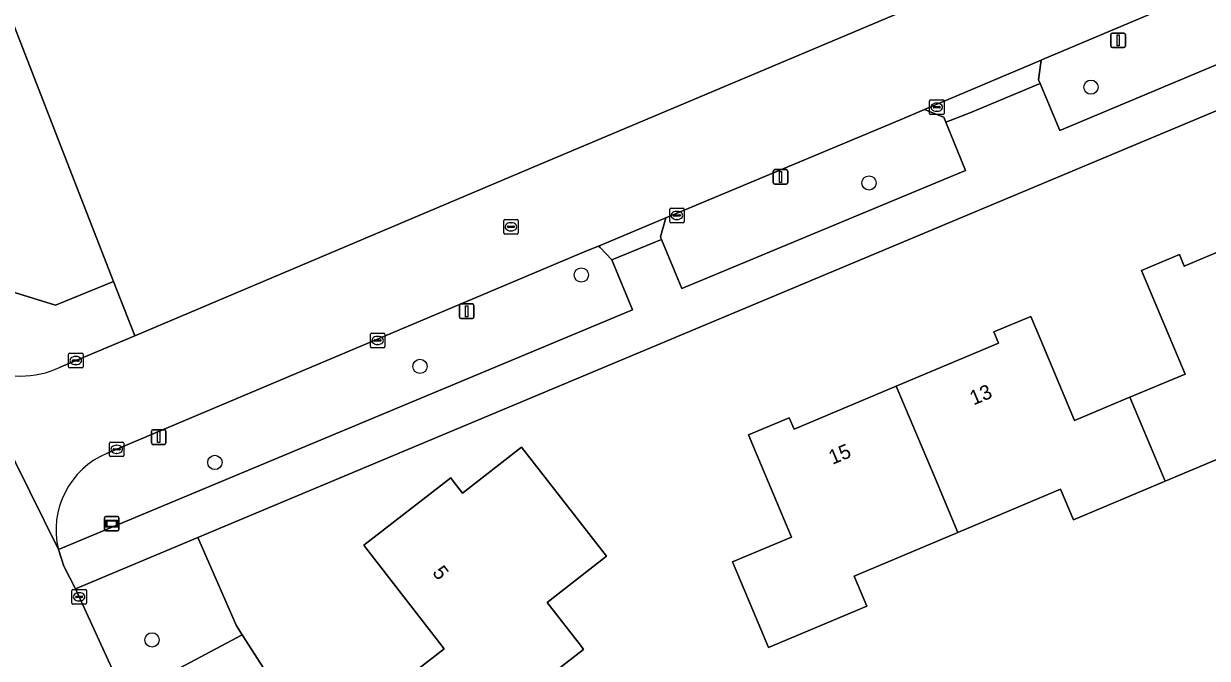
# Model space of a CAD drawing. Extents: x 162417 to 163722, y 384268 to 385417.
# Drawn here: x 163351.6 to 163432.7, y 384965.6 to 385009.1 of the extents above; entities that cross this region are included whole.
import ezdxf

# ---------------------------------------------------------------- set-up
doc = ezdxf.new("R2010")
doc.units = 0
for name, color, linetype in [('IMGEO_Berm_groen', 7, 'Continuous'), ('IMGEO_Boom', 7, 'Continuous'), ('IMGEO_Erf', 7, 'Continuous'), ('IMGEO_Groenvoorziening', 7, 'Continuous'), ('IMGEO_Kolk', 7, 'Continuous'), ('IMGEO_Lichtmast', 7, 'Continuous'), ('IMGEO_Loofbos', 7, 'Continuous'), ('IMGEO_Pand', 7, 'Continuous'), ('IMGEO_Pand_nummerreeks', 7, 'Continuous'), ('IMGEO_Rijbaan_lokaal_gesloten', 7, 'Continuous'), ('IMGEO_Rioolput', 7, 'Continuous'), ('IMGEO_Verklikker', 7, 'Continuous'), ('IMGEO_Voetpad_open', 7, 'Continuous')]:
    doc.layers.add(name, color=color, linetype=linetype)

msp = doc.modelspace()

# ---------------------------------------------------------------- linework, layer by layer
at = {"layer": 'IMGEO_Berm_groen'}
for points in [[(163354.083, 384985.536), (163359.186, 384987.697), (163357.745, 384991.405), (163353.753, 384989.786), (163350.645, 384990.763), (163348.459, 384993.49), (163345.34, 385000), (163325.132, 385042.177)], [(163393.318, 384989.467), (163391.91, 384992.911), (163391.091, 384993.737), (163390.981, 384993.848), (163390.13, 384993.491), (163357.952, 384979.9), (163357.313, 384979.632)], [(163353.956, 384973.02), (163393.318, 384989.467)]]:
    msp.add_lwpolyline(points, dxfattribs=at)
msp.add_lwpolyline([(163442.302, 385013.957), (163442.198, 385014.207), (163441.445, 385014.752), (163441.213, 385014.921), (163429.137, 385009.898), (163421.429, 385006.64), (163421.331, 385006.599), (163421.165, 385005.249), (163421.266, 385005.008), (163422.621, 385001.771), (163443.689, 385010.64)], close=True, dxfattribs=at)
for centre, radius, start, end in [((163351.397, 384991.135), 6.21, 243.35069, 295.62302), ((163359.493, 384974.367), 5.698, 112.49155, 193.67343)]:
    msp.add_arc(centre, radius, start, end, dxfattribs=at)
at = {"layer": 'IMGEO_Boom'}
for centre in [(163424.753, 385004.752), (163409.535, 384998.178), (163389.81, 384991.862), (163378.747, 384985.59), (163364.685, 384978.999), (163360.375, 384966.821)]:
    msp.add_circle(centre, 0.489, dxfattribs=at)
at = {"layer": 'IMGEO_Erf'}
for points in [[(163526.981, 385058.237), (163524.402, 385063.53), (163507.868, 385095.856), (163500, 385092.556), (163419.878, 385059.084), (163371.144, 385038.583), (163343.981, 385026.826), (163354.406, 385000), (163357.745, 384991.405), (163359.186, 384987.697), (163387.545, 384999.704), (163388.243, 385000), (163425.932, 385015.904), (163500, 385046.827), (163524.917, 385057.312)], [(163383.993, 384961.544), (163380.314, 384958.697), (163380.225, 384958.812), (163376.874, 384963.141), (163376.718, 384963.343), (163380.414, 384966.203), (163375.046, 384973.139), (163374.9, 384973.327), (163380.856, 384977.937), (163381.023, 384977.723), (163381.669, 384976.895), (163385.708, 384980.043), (163391.542, 384972.558), (163387.465, 384969.38), (163389.817, 384966.363), (163389.969, 384966.169)]]:
    msp.add_lwpolyline(points, close=True, dxfattribs=at)
for points in [[(163571.782, 384971.962), (163557.559, 385000), (163534.443, 385045.503), (163500, 385031.078), (163425.859, 385000), (163365.371, 384974.629), (163363.507, 384973.847), (163366.161, 384967.778), (163366.55, 384967.171), (163368.242, 384964.531)], [(163436.151, 384980.365), (163429.839, 384977.706), (163423.549, 384975.056), (163422.664, 384977.156), (163415.628, 384974.192), (163408.509, 384971.193), (163409.376, 384969.136), (163402.648, 384966.302), (163402.116, 384967.566), (163400.175, 384972.173), (163404.216, 384973.876), (163401.795, 384979.625), (163401.263, 384980.887), (163404.062, 384982.066), (163404.393, 384981.278), (163411.402, 384984.231), (163418.408, 384987.182), (163418.084, 384987.951), (163420.62, 384989.019), (163421.195, 384987.655), (163423.631, 384981.873), (163427.308, 384983.422), (163427.415, 384983.467), (163431.202, 384985.062), (163428.209, 384992.166), (163430.816, 384993.264), (163431.151, 384992.468), (163438.083, 384995.389)]]:
    msp.add_lwpolyline(points, dxfattribs=at)
at = {"layer": 'IMGEO_Groenvoorziening'}
for points in [[(163416.143, 384999.038), (163414.794, 385002.353), (163414.657, 385002.69), (163414.525, 385002.749), (163413.564, 385003.127), (163413.331, 385003.218), (163411.617, 385002.494), (163395.6, 384995.783), (163395.23, 384994.489), (163395.315, 384994.288), (163396.712, 384990.944)], [(163363.507, 384973.847), (163355.13, 384970.334), (163358.119, 384963.778), (163359.376, 384963.356), (163366.55, 384967.171), (163366.161, 384967.778)]]:
    msp.add_lwpolyline(points, close=True, dxfattribs=at)
at = {"layer": 'IMGEO_Kolk'}
for p, q in [((163413.678, 385002.947), (163413.678, 385003.799)), ((163413.753, 385003.873), (163414.605, 385003.873)), ((163413.937, 385003.367), (163413.937, 385003.379)), ((163414.375, 385003.33), (163413.977, 385003.33)), ((163413.98, 385003.416), (163414.378, 385003.416)), ((163414.166, 385003.653), (163414.191, 385003.653)), ((163414.421, 385003.379), (163414.421, 385003.367)), ((163414.679, 385003.799), (163414.679, 385002.947)), ((163414.605, 385002.873), (163413.753, 385002.873)), ((163414.189, 385003.093), (163414.164, 385003.093)), ((163395.868, 384995.524), (163395.868, 384996.376)), ((163395.943, 384996.45), (163396.795, 384996.45)), ((163396.356, 384996.23), (163396.381, 384996.23)), ((163396.869, 384996.376), (163396.869, 384995.524)), ((163396.795, 384995.45), (163395.943, 384995.45)), ((163396.127, 384995.944), (163396.127, 384995.956)), ((163396.565, 384995.907), (163396.167, 384995.907)), ((163396.17, 384995.993), (163396.568, 384995.993)), ((163396.379, 384995.67), (163396.354, 384995.67)), ((163396.611, 384995.956), (163396.611, 384995.944)), ((163375.345, 384986.944), (163375.345, 384987.796)), ((163375.42, 384987.87), (163376.272, 384987.87)), ((163375.604, 384987.364), (163375.604, 384987.376)), ((163376.042, 384987.327), (163375.644, 384987.327)), ((163375.647, 384987.413), (163376.045, 384987.413)), ((163375.856, 384987.09), (163375.831, 384987.09)), ((163375.833, 384987.65), (163375.858, 384987.65)), ((163376.088, 384987.376), (163376.088, 384987.364)), ((163376.346, 384987.796), (163376.346, 384986.944)), ((163354.644, 384985.563), (163354.644, 384986.415)), ((163354.719, 384986.489), (163355.571, 384986.489)), ((163355.132, 384986.269), (163355.157, 384986.269)), ((163355.645, 384986.415), (163355.645, 384985.563)), ((163376.272, 384986.87), (163375.42, 384986.87)), ((163355.571, 384985.489), (163354.719, 384985.489)), ((163354.903, 384985.983), (163354.903, 384985.995)), ((163355.341, 384985.946), (163354.943, 384985.946)), ((163354.946, 384986.032), (163355.344, 384986.032)), ((163355.155, 384985.709), (163355.13, 384985.709)), ((163355.387, 384985.995), (163355.387, 384985.983)), ((163357.451, 384979.474), (163357.451, 384980.326)), ((163357.526, 384980.4), (163358.378, 384980.4)), ((163357.71, 384979.894), (163357.71, 384979.906)), ((163358.148, 384979.857), (163357.75, 384979.857)), ((163357.753, 384979.943), (163358.151, 384979.943)), ((163357.939, 384980.18), (163357.964, 384980.18)), ((163358.194, 384979.906), (163358.194, 384979.894)), ((163358.452, 384980.326), (163358.452, 384979.474)), ((163358.378, 384979.4), (163357.526, 384979.4)), ((163357.962, 384979.62), (163357.937, 384979.62)), ((163354.878, 384969.351), (163354.878, 384970.203)), ((163354.953, 384970.277), (163355.805, 384970.277)), ((163355.366, 384970.057), (163355.391, 384970.057)), ((163355.879, 384970.203), (163355.879, 384969.351)), ((163355.805, 384969.277), (163354.953, 384969.277)), ((163355.137, 384969.771), (163355.137, 384969.783)), ((163355.575, 384969.734), (163355.177, 384969.734)), ((163355.18, 384969.82), (163355.578, 384969.82)), ((163355.389, 384969.497), (163355.364, 384969.497)), ((163355.621, 384969.783), (163355.621, 384969.771))]:
    msp.add_line(p, q, dxfattribs=at)
for points in [[(163413.678, 385002.947), (163413.678, 385003.799)], [(163413.753, 385003.873), (163414.605, 385003.873)], [(163414.679, 385003.799), (163414.679, 385002.947)], [(163414.605, 385002.873), (163413.753, 385002.873)], [(163395.868, 384995.524), (163395.868, 384996.376)], [(163395.943, 384996.45), (163396.795, 384996.45)], [(163396.869, 384996.376), (163396.869, 384995.524)], [(163396.795, 384995.45), (163395.943, 384995.45)], [(163375.345, 384986.944), (163375.345, 384987.796)], [(163375.42, 384987.87), (163376.272, 384987.87)], [(163376.346, 384987.796), (163376.346, 384986.944)], [(163354.644, 384985.563), (163354.644, 384986.415)], [(163354.719, 384986.489), (163355.571, 384986.489)], [(163355.645, 384986.415), (163355.645, 384985.563)], [(163376.272, 384986.87), (163375.42, 384986.87)], [(163355.571, 384985.489), (163354.719, 384985.489)], [(163357.451, 384979.474), (163357.451, 384980.326)], [(163357.526, 384980.4), (163358.378, 384980.4)], [(163358.452, 384980.326), (163358.452, 384979.474)], [(163358.378, 384979.4), (163357.526, 384979.4)], [(163354.878, 384969.351), (163354.878, 384970.203)], [(163354.953, 384970.277), (163355.805, 384970.277)], [(163355.879, 384970.203), (163355.879, 384969.351)], [(163355.805, 384969.277), (163354.953, 384969.277)]]:
    msp.add_lwpolyline(points, dxfattribs=at)
for centre, radius, start, end in [((163413.755, 385003.797), 0.0765, 91.55205, 178.44795), ((163413.755, 385003.797), 0.0765, 91.55205, 178.44795), ((163413.977, 385003.376), 0.0403, 85.87752, 175.75265), ((163413.974, 385003.366), 0.0366, 178.93798, 274.71019), ((163414.378, 385003.373), 0.043, 264.86636, 352.45326), ((163414.382, 385003.378), 0.0386, 1.73085, 96.63898), ((163414.603, 385003.797), 0.0765, 1.55205, 88.44795), ((163414.603, 385003.797), 0.0765, 1.55205, 88.44795), ((163413.755, 385002.949), 0.0765, 181.55205, 268.44795), ((163413.755, 385002.949), 0.0765, 181.55205, 268.44795), ((163414.603, 385002.949), 0.0765, 271.55205, 358.44795), ((163414.603, 385002.949), 0.0765, 271.55205, 358.44795), ((163395.945, 384996.374), 0.0765, 91.55205, 178.44795), ((163395.945, 384996.374), 0.0765, 91.55205, 178.44795), ((163396.793, 384996.374), 0.0765, 1.55205, 88.44795), ((163396.793, 384996.374), 0.0765, 1.55205, 88.44795), ((163395.945, 384995.526), 0.0765, 181.55205, 268.44795), ((163395.945, 384995.526), 0.0765, 181.55205, 268.44795), ((163396.167, 384995.953), 0.0403, 85.87752, 175.75265), ((163396.164, 384995.943), 0.0366, 178.93798, 274.71019), ((163396.568, 384995.95), 0.043, 264.86636, 352.45326), ((163396.572, 384995.955), 0.0386, 1.73085, 96.63898), ((163396.793, 384995.526), 0.0765, 271.55205, 358.44795), ((163396.793, 384995.526), 0.0765, 271.55205, 358.44795), ((163375.422, 384987.794), 0.0765, 91.55205, 178.44795), ((163375.422, 384987.794), 0.0765, 91.55205, 178.44795), ((163375.644, 384987.373), 0.0403, 85.87752, 175.75265), ((163375.641, 384987.363), 0.0366, 178.93798, 274.71019), ((163376.045, 384987.37), 0.043, 264.86636, 352.45326), ((163376.049, 384987.375), 0.0386, 1.73085, 96.63898), ((163376.27, 384987.794), 0.0765, 1.55205, 88.44795), ((163376.27, 384987.794), 0.0765, 1.55205, 88.44795), ((163354.721, 384986.413), 0.0765, 91.55205, 178.44795), ((163354.721, 384986.413), 0.0765, 91.55205, 178.44795), ((163355.569, 384986.413), 0.0765, 1.55205, 88.44795), ((163355.569, 384986.413), 0.0765, 1.55205, 88.44795), ((163375.422, 384986.946), 0.0765, 181.55205, 268.44795), ((163375.422, 384986.946), 0.0765, 181.55205, 268.44795), ((163376.27, 384986.946), 0.0765, 271.55205, 358.44795), ((163376.27, 384986.946), 0.0765, 271.55205, 358.44795), ((163354.721, 384985.565), 0.0765, 181.55205, 268.44795), ((163354.721, 384985.565), 0.0765, 181.55205, 268.44795), ((163354.943, 384985.992), 0.0403, 85.87752, 175.75265), ((163354.94, 384985.982), 0.0366, 178.93798, 274.71019), ((163355.344, 384985.989), 0.043, 264.86636, 352.45326), ((163355.348, 384985.994), 0.0386, 1.73085, 96.63898), ((163355.569, 384985.565), 0.0765, 271.55205, 358.44795), ((163355.569, 384985.565), 0.0765, 271.55205, 358.44795), ((163357.528, 384980.324), 0.0765, 91.55205, 178.44795), ((163357.528, 384980.324), 0.0765, 91.55205, 178.44795), ((163357.75, 384979.903), 0.0403, 85.87752, 175.75265), ((163357.747, 384979.893), 0.0366, 178.93798, 274.71019), ((163358.151, 384979.9), 0.043, 264.86636, 352.45326), ((163358.155, 384979.905), 0.0386, 1.73085, 96.63898), ((163358.376, 384980.324), 0.0765, 1.55205, 88.44795), ((163358.376, 384980.324), 0.0765, 1.55205, 88.44795), ((163357.528, 384979.476), 0.0765, 181.55205, 268.44795), ((163357.528, 384979.476), 0.0765, 181.55205, 268.44795), ((163358.376, 384979.476), 0.0765, 271.55205, 358.44795), ((163358.376, 384979.476), 0.0765, 271.55205, 358.44795), ((163354.955, 384970.201), 0.0765, 91.55205, 178.44795), ((163354.955, 384970.201), 0.0765, 91.55205, 178.44795), ((163355.803, 384970.201), 0.0765, 1.55205, 88.44795), ((163355.803, 384970.201), 0.0765, 1.55205, 88.44795), ((163354.955, 384969.353), 0.0765, 181.55205, 268.44795), ((163354.955, 384969.353), 0.0765, 181.55205, 268.44795), ((163355.177, 384969.78), 0.0403, 85.87752, 175.75265), ((163355.174, 384969.77), 0.0366, 178.93798, 274.71019), ((163355.578, 384969.777), 0.043, 264.86636, 352.45326), ((163355.582, 384969.782), 0.0386, 1.73085, 96.63898), ((163355.803, 384969.353), 0.0765, 271.55205, 358.44795), ((163355.803, 384969.353), 0.0765, 271.55205, 358.44795)]:
    msp.add_arc(centre, radius, start, end, dxfattribs=at)
for centre, major_axis, ratio, start_param, end_param in [((163414.165, 385003.373), (-0.387, 0.002), 0.722429, 4.712389, 7.853982), ((163414.19, 385003.373), (-0.39, 0.002), 0.717154, 1.570796, 4.712389), ((163396.355, 384995.95), (-0.387, 0.002), 0.722429, 4.712389, 7.853982), ((163396.38, 384995.95), (-0.39, 0.002), 0.717154, 1.570796, 4.712389), ((163375.832, 384987.37), (-0.387, 0.002), 0.722429, 4.712389, 7.853982), ((163375.857, 384987.37), (-0.39, 0.002), 0.717154, 1.570796, 4.712389), ((163355.131, 384985.989), (-0.387, 0.002), 0.722429, 4.712389, 7.853982), ((163355.156, 384985.989), (-0.39, 0.002), 0.717154, 1.570796, 4.712389), ((163357.938, 384979.9), (-0.387, 0.002), 0.722429, 4.712389, 7.853982), ((163357.963, 384979.9), (-0.39, 0.002), 0.717154, 1.570796, 4.712389), ((163355.365, 384969.777), (-0.387, 0.002), 0.722429, 4.712389, 7.853982), ((163355.39, 384969.777), (-0.39, 0.002), 0.717154, 1.570796, 4.712389)]:
    msp.add_ellipse(centre, major_axis=major_axis, ratio=ratio, start_param=start_param, end_param=end_param, dxfattribs=at)
at = {"layer": 'IMGEO_Lichtmast'}
for p, q in [((163426.121, 385007.567), (163426.121, 385008.367)), ((163426.121, 385008.367), (163426.121, 385007.567)), ((163426.221, 385008.467), (163427.011, 385008.467)), ((163427.011, 385008.467), (163426.221, 385008.467)), ((163427.111, 385008.367), (163427.111, 385007.567)), ((163427.111, 385007.567), (163427.111, 385008.367)), ((163427.011, 385007.467), (163426.221, 385007.467)), ((163426.221, 385007.467), (163427.011, 385007.467)), ((163402.971, 384998.194), (163402.971, 384998.994)), ((163402.971, 384998.994), (163402.971, 384998.194)), ((163403.071, 384999.094), (163403.861, 384999.094)), ((163403.861, 384999.094), (163403.071, 384999.094)), ((163403.961, 384998.994), (163403.961, 384998.194)), ((163403.961, 384998.194), (163403.961, 384998.994)), ((163403.861, 384998.094), (163403.071, 384998.094)), ((163403.071, 384998.094), (163403.861, 384998.094)), ((163381.45, 384988.975), (163381.45, 384989.775)), ((163381.45, 384989.775), (163381.45, 384988.975)), ((163381.55, 384989.875), (163382.34, 384989.875)), ((163382.34, 384989.875), (163381.55, 384989.875)), ((163382.44, 384989.775), (163382.44, 384988.975)), ((163382.44, 384988.975), (163382.44, 384989.775)), ((163382.34, 384988.875), (163381.55, 384988.875)), ((163381.55, 384988.875), (163382.34, 384988.875)), ((163360.335, 384980.341), (163360.335, 384981.141)), ((163360.335, 384981.141), (163360.335, 384980.341)), ((163360.435, 384981.241), (163361.225, 384981.241)), ((163361.225, 384981.241), (163360.435, 384981.241)), ((163361.325, 384981.141), (163361.325, 384980.341)), ((163361.325, 384980.341), (163361.325, 384981.141)), ((163361.225, 384980.241), (163360.435, 384980.241)), ((163360.435, 384980.241), (163361.225, 384980.241))]:
    msp.add_line(p, q, dxfattribs=at)
for points in [[(163426.541, 385008.342), (163426.691, 385008.342), (163426.691, 385007.592), (163426.541, 385007.592), (163426.541, 385008.342)], [(163403.391, 384998.969), (163403.541, 384998.969), (163403.541, 384998.219), (163403.391, 384998.219), (163403.391, 384998.969)], [(163381.87, 384989.75), (163382.02, 384989.75), (163382.02, 384989), (163381.87, 384989), (163381.87, 384989.75)], [(163360.755, 384981.116), (163360.905, 384981.116), (163360.905, 384980.366), (163360.755, 384980.366), (163360.755, 384981.116)]]:
    msp.add_lwpolyline(points, dxfattribs=at)
for centre, start, end in [((163426.221, 385008.367), 90, 180), ((163426.221, 385008.367), 90, 180), ((163427.011, 385008.367), 0, 90), ((163427.011, 385008.367), 360, 90), ((163426.221, 385007.567), 180, 270), ((163426.221, 385007.567), 180, 270), ((163427.011, 385007.567), 270, 0), ((163427.011, 385007.567), 270, 0), ((163403.071, 384998.994), 90, 180), ((163403.071, 384998.994), 90, 180), ((163403.861, 384998.994), 0, 90), ((163403.861, 384998.994), 360, 90), ((163403.071, 384998.194), 180, 270), ((163403.071, 384998.194), 180, 270), ((163403.861, 384998.194), 270, 0), ((163403.861, 384998.194), 270, 0), ((163381.55, 384989.775), 90, 180), ((163381.55, 384989.775), 90, 180), ((163382.34, 384989.775), 0, 90), ((163382.34, 384989.775), 360, 90), ((163381.55, 384988.975), 180, 270), ((163381.55, 384988.975), 180, 270), ((163382.34, 384988.975), 270, 0), ((163382.34, 384988.975), 270, 0), ((163360.435, 384981.141), 90, 180), ((163360.435, 384981.141), 90, 180), ((163361.225, 384981.141), 0, 90), ((163361.225, 384981.141), 360, 90), ((163360.435, 384980.341), 180, 270), ((163360.435, 384980.341), 180, 270), ((163361.225, 384980.341), 270, 0), ((163361.225, 384980.341), 270, 0)]:
    msp.add_arc(centre, 0.1, start, end, dxfattribs=at)
at = {"layer": 'IMGEO_Loofbos'}
msp.add_lwpolyline([(163460.206, 385094.129), (163435.738, 385083.799), (163412.002, 385074.664), (163384.948, 385064.683), (163369.084, 385058.609), (163325.132, 385042.177), (163345.34, 385000), (163348.459, 384993.49), (163350.645, 384990.763), (163353.753, 384989.786), (163357.745, 384991.405), (163354.406, 385000), (163343.981, 385026.826), (163371.144, 385038.583), (163419.878, 385059.084), (163500, 385092.556)], dxfattribs=at)
at = {"layer": 'IMGEO_Pand'}
for points in [[(163438.083, 384995.389), (163431.151, 384992.468), (163430.816, 384993.264), (163428.209, 384992.166), (163431.202, 384985.062), (163427.415, 384983.467), (163429.839, 384977.706), (163436.151, 384980.365), (163433.747, 384986.07), (163440.763, 384989.026)], [(163429.839, 384977.706), (163427.415, 384983.467), (163427.308, 384983.422), (163423.631, 384981.873), (163421.195, 384987.655), (163420.62, 384989.019), (163418.084, 384987.951), (163418.408, 384987.182), (163411.402, 384984.231), (163414.062, 384977.913), (163415.628, 384974.192), (163422.664, 384977.156), (163423.549, 384975.056)], [(163408.509, 384971.193), (163415.628, 384974.192), (163414.062, 384977.913), (163411.402, 384984.231), (163404.393, 384981.278), (163404.062, 384982.066), (163401.263, 384980.887), (163401.795, 384979.625), (163404.216, 384973.876), (163400.175, 384972.173), (163402.116, 384967.566), (163402.648, 384966.302), (163409.376, 384969.136)], [(163383.993, 384961.544), (163389.969, 384966.169), (163389.817, 384966.363), (163387.465, 384969.38), (163391.542, 384972.558), (163385.708, 384980.043), (163381.669, 384976.895), (163381.023, 384977.723), (163380.856, 384977.937), (163374.9, 384973.327), (163375.046, 384973.139), (163380.414, 384966.203), (163376.718, 384963.343), (163376.874, 384963.141), (163380.225, 384958.812), (163380.314, 384958.697)]]:
    msp.add_lwpolyline(points, close=True, dxfattribs=at)
at = {"layer": 'IMGEO_Rijbaan_lokaal_gesloten'}
for points in [[(163527.71, 385058.563), (163526.981, 385058.237), (163524.917, 385057.312), (163500, 385046.827), (163425.932, 385015.904), (163388.243, 385000), (163387.545, 384999.704), (163359.186, 384987.697), (163354.083, 384985.536)], [(163357.313, 384979.632), (163357.952, 384979.9), (163390.13, 384993.491), (163390.981, 384993.848), (163394.735, 384995.421), (163395.6, 384995.783), (163411.617, 385002.494), (163413.331, 385003.218), (163421.331, 385006.599), (163421.429, 385006.64), (163429.137, 385009.898), (163441.213, 385014.921), (163448.57, 385017.982), (163468.504, 385026.389)], [(163348.551, 384967.508), (163351.64, 384961.227), (163361.182, 384941.826), (163363.047, 384938.292), (163366.713, 384931.978), (163372.616, 384935.569), (163372.231, 384936.23), (163370.281, 384939.578), (163363.764, 384952.168), (163360.184, 384959.531), (163358.119, 384963.778), (163355.13, 384970.334), (163354.334, 384971.888), (163353.956, 384973.02), (163347.053, 384986.951)], [(163347.053, 384986.951), (163353.956, 384973.02)]]:
    msp.add_lwpolyline(points, dxfattribs=at)
for centre, radius, start, end in [((163351.397, 384991.135), 6.21, 243.35069, 295.62302), ((163359.493, 384974.367), 5.698, 112.49155, 193.67343)]:
    msp.add_arc(centre, radius, start, end, dxfattribs=at)
at = {"layer": 'IMGEO_Rioolput'}
for p, q in [((163384.487, 384994.744), (163384.487, 384995.596)), ((163384.562, 384995.67), (163385.414, 384995.67)), ((163384.789, 384995.213), (163385.187, 384995.213)), ((163384.975, 384995.45), (163385, 384995.45)), ((163385.488, 384995.596), (163385.488, 384994.744)), ((163385.414, 384994.67), (163384.562, 384994.67)), ((163384.746, 384995.164), (163384.746, 384995.176)), ((163385.184, 384995.127), (163384.786, 384995.127)), ((163384.998, 384994.89), (163384.973, 384994.89)), ((163385.23, 384995.176), (163385.23, 384995.164))]:
    msp.add_line(p, q, dxfattribs=at)
for points in [[(163384.487, 384994.744), (163384.487, 384995.596)], [(163384.562, 384995.67), (163385.414, 384995.67)], [(163385.488, 384995.596), (163385.488, 384994.744)], [(163385.414, 384994.67), (163384.562, 384994.67)]]:
    msp.add_lwpolyline(points, dxfattribs=at)
for centre, radius, start, end in [((163384.564, 384995.594), 0.0765, 91.55205, 178.44795), ((163384.564, 384995.594), 0.0765, 91.55205, 178.44795), ((163384.786, 384995.173), 0.0403, 85.87752, 175.75265), ((163385.191, 384995.175), 0.0386, 1.73085, 96.63898), ((163385.412, 384995.594), 0.0765, 1.55205, 88.44795), ((163385.412, 384995.594), 0.0765, 1.55205, 88.44795), ((163384.564, 384994.746), 0.0765, 181.55205, 268.44795), ((163384.564, 384994.746), 0.0765, 181.55205, 268.44795), ((163384.783, 384995.163), 0.0366, 178.93798, 274.71019), ((163385.187, 384995.17), 0.043, 264.86636, 352.45326), ((163385.412, 384994.746), 0.0765, 271.55205, 358.44795), ((163385.412, 384994.746), 0.0765, 271.55205, 358.44795)]:
    msp.add_arc(centre, radius, start, end, dxfattribs=at)
for centre, major_axis, ratio, start_param, end_param in [((163384.974, 384995.17), (-0.387, 0.002), 0.722429, 4.712389, 7.853982), ((163384.999, 384995.17), (-0.39, 0.002), 0.717154, 1.570796, 4.712389)]:
    msp.add_ellipse(centre, major_axis=major_axis, ratio=ratio, start_param=start_param, end_param=end_param, dxfattribs=at)
at = {"layer": 'IMGEO_Verklikker'}
for p, q in [((163357.118, 384974.396), (163357.118, 384975.196)), ((163357.118, 384975.196), (163357.118, 384974.396)), ((163357.218, 384975.296), (163358.008, 384975.296)), ((163358.008, 384975.296), (163357.218, 384975.296)), ((163358.108, 384975.196), (163358.108, 384974.396)), ((163358.108, 384974.396), (163358.108, 384975.196)), ((163358.008, 384974.296), (163357.218, 384974.296)), ((163357.218, 384974.296), (163358.008, 384974.296))]:
    msp.add_line(p, q, dxfattribs=at)
for points in [[(163357.219, 384975.028), (163358.007, 384975.028), (163358.007, 384974.564), (163357.219, 384974.564), (163357.219, 384975.028)], [(163357.284, 384974.963), (163357.284, 384974.629), (163357.942, 384974.629), (163357.942, 384974.963), (163357.284, 384974.963)]]:
    msp.add_lwpolyline(points, dxfattribs=at)
for centre, start, end in [((163357.218, 384975.196), 90, 180), ((163357.218, 384975.196), 90, 180), ((163358.008, 384975.196), 0, 90), ((163358.008, 384975.196), 360, 90), ((163357.218, 384974.396), 180, 270), ((163357.218, 384974.396), 180, 270), ((163358.008, 384974.396), 270, 0), ((163358.008, 384974.396), 270, 0)]:
    msp.add_arc(centre, 0.1, start, end, dxfattribs=at)
at = {"layer": 'IMGEO_Voetpad_open'}
msp.add_lwpolyline([(163443.689, 385010.64), (163422.621, 385001.771), (163421.266, 385005.008), (163416.409, 385002.969), (163414.794, 385002.353), (163416.143, 384999.038), (163396.712, 384990.944), (163395.315, 384994.288), (163391.91, 384992.911), (163393.318, 384989.467), (163353.956, 384973.02), (163354.334, 384971.888), (163355.13, 384970.334), (163363.507, 384973.847), (163365.371, 384974.629), (163425.859, 385000), (163500, 385031.078)], dxfattribs=at)
for points in [[(163421.266, 385005.008), (163421.165, 385005.249), (163421.331, 385006.599), (163413.331, 385003.218), (163413.564, 385003.127), (163414.525, 385002.749), (163414.657, 385002.69), (163414.794, 385002.353), (163416.409, 385002.969)], [(163395.315, 384994.288), (163395.23, 384994.489), (163395.6, 384995.783), (163394.735, 384995.421), (163390.981, 384993.848), (163391.091, 384993.737), (163391.91, 384992.911)], [(163366.55, 384967.171), (163359.376, 384963.356), (163358.119, 384963.778), (163360.184, 384959.531), (163368.242, 384964.531)]]:
    msp.add_lwpolyline(points, close=True, dxfattribs=at)

# ---------------------------------------------------------------- texts
at = {"layer": 'IMGEO_Pand_nummerreeks'}
for s, rotation, p in [('13', 22.84389, (163416.701, 384982.905)), ('15', 22.84389, (163407.027, 384978.829)), ('5', 307.73479, (163379.554, 384971.432))]:
    msp.add_text(s, height=1, rotation=rotation, dxfattribs=at).set_placement(p)

doc.saveas('drawing.dxf')
